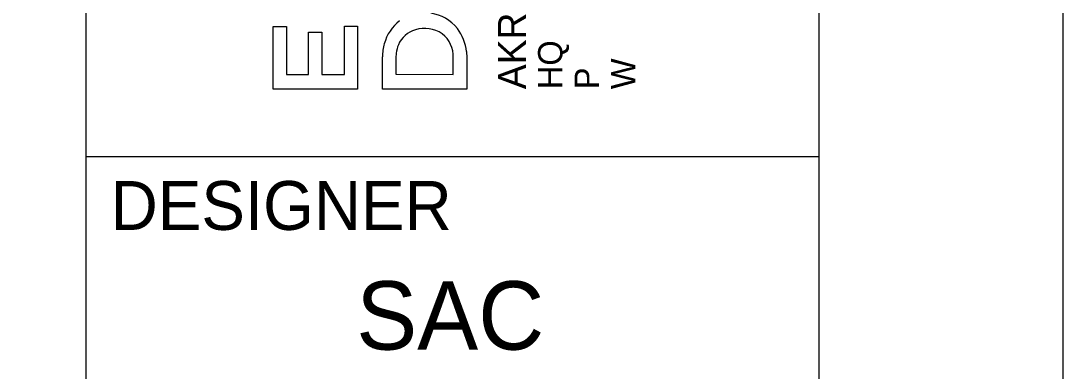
# Model space of a CAD drawing. Extents: x -0.1 to 34, y 0 to 22.
# Drawn here: x 31.866 to 34, y 2.061 to 2.778 of the extents above; entities that cross this region are included whole.
import ezdxf

# ---------------------------------------------------------------- set-up
doc = ezdxf.new("R2010")
doc.units = 0
for name, color, linetype in [('SH_Border', 7, 'Continuous'), ('SH_Cut_Line', 7, 'Continuous'), ('SH_Data', 7, 'Continuous')]:
    doc.layers.add(name, color=color, linetype=linetype)

msp = doc.modelspace()

# ---------------------------------------------------------------- linework, layer by layer
at = {"layer": 'SH_Border'}
for p, q in [((32, 0.5), (32, 21.5)), ((32, 2.5), (33.5, 2.5))]:
    msp.add_line(p, q, dxfattribs=at)
msp.add_lwpolyline([(1.5, 21.5), (33.5, 21.5), (33.5, 0.5), (1.5, 0.5)], close=True, dxfattribs=at)
at = {"layer": 'SH_Cut_Line'}
msp.add_lwpolyline([(0, 0), (34, 0), (34, 22), (0, 22)], close=True, dxfattribs=at)
at = {"layer": 'SH_Data'}
for p, q in [((32.383, 2.6379), (32.383, 2.766)), ((32.383, 2.766), (32.4101, 2.766)), ((32.4101, 2.766), (32.4101, 2.6683)), ((32.455, 2.6683), (32.455, 2.7549)), ((32.455, 2.7549), (32.4822, 2.7549)), ((32.4822, 2.7549), (32.4822, 2.6683)), ((32.5286, 2.6683), (32.5286, 2.7672)), ((32.5286, 2.7672), (32.5557, 2.7672)), ((32.5557, 2.7672), (32.5557, 2.6379)), ((32.6347, 2.7118), (32.6341, 2.7023)), ((32.7785, 2.715), (32.7792, 2.7021)), ((32.6064, 2.638), (32.6064, 2.704)), ((32.6341, 2.7023), (32.6341, 2.6684)), ((32.7515, 2.6683), (32.7515, 2.7024)), ((32.7792, 2.7021), (32.7792, 2.638)), ((32.4101, 2.6683), (32.455, 2.6683)), ((32.4822, 2.6683), (32.5286, 2.6683)), ((32.6341, 2.6684), (32.7515, 2.6683)), ((32.5557, 2.6379), (32.383, 2.6379)), ((32.7792, 2.638), (32.6064, 2.638))]:
    msp.add_line(p, q, dxfattribs=at)
msp.add_lwpolyline([(32.383, 2.6379), (32.383, 2.766), (32.4101, 2.766), (32.4101, 2.6683), (32.455, 2.6683), (32.455, 2.7549), (32.4822, 2.7549), (32.4822, 2.6683), (32.5286, 2.6683), (32.5286, 2.7672), (32.5557, 2.7672), (32.5557, 2.6379)], close=True, dxfattribs=at)
for points in [[(32.7785, 2.715), (32.7792, 2.7021), (32.7792, 2.638), (32.6064, 2.638)], [(32.6347, 2.7118), (32.6341, 2.7023), (32.6341, 2.6684), (32.7515, 2.6683), (32.7515, 2.7024)], [(32.6064, 2.638), (32.6064, 2.704)]]:
    msp.add_lwpolyline(points, dxfattribs=at)
for centre, radius, start, end in [((32.6939, 2.7089), 0.0865, 127.2362, 165.148), ((32.6939, 2.7089), 0.0865, 127.2362, 165.148), ((32.6946, 2.7113), 0.0827, 37.8521, 82.402), ((32.6946, 2.7113), 0.0827, 37.8521, 82.402), ((32.6889, 2.7078), 0.054, 106.1881, 157.3861), ((32.6889, 2.7078), 0.054, 106.1881, 157.3861), ((32.6928, 2.6986), 0.0639, 55.6727, 107.2093), ((32.6928, 2.6986), 0.0639, 55.6727, 107.2093), ((32.6859, 2.7057), 0.0931, 5.7333, 37.304), ((32.6859, 2.7057), 0.0931, 5.7333, 37.304), ((32.6929, 2.705), 0.0587, 357.4662, 52.2665), ((32.6929, 2.705), 0.0587, 357.4662, 52.2665), ((32.7143, 2.7028), 0.1078, 164.7861, 179.3704), ((32.7143, 2.7028), 0.1078, 164.7861, 179.3704), ((32.6983, 2.7039), 0.0641, 157.3571, 172.9275), ((32.6983, 2.7039), 0.0641, 157.3571, 172.9275)]:
    msp.add_arc(centre, radius, start, end, dxfattribs=at)

# ---------------------------------------------------------------- texts
for s, height, p in [('AKRON / CLEVELAND / COLUMBUS', 0.056969, (32.9001, 2.638)), ('HQ ', 0.04985, (32.9749, 2.638)), ('W', 0.0498, (33.1244, 2.638)), ('P', 0.0498, (33.0497, 2.638))]:
    msp.add_text(s, height=height, rotation=90, dxfattribs=at).set_placement(p)
for s, height, p in [('DESIGNER', 0.1, (32.05, 2.35)), ('SAC', 0.14, (32.5528, 2.105))]:
    msp.add_text(s, height=height, dxfattribs=at).set_placement(p)

doc.saveas('drawing.dxf')
